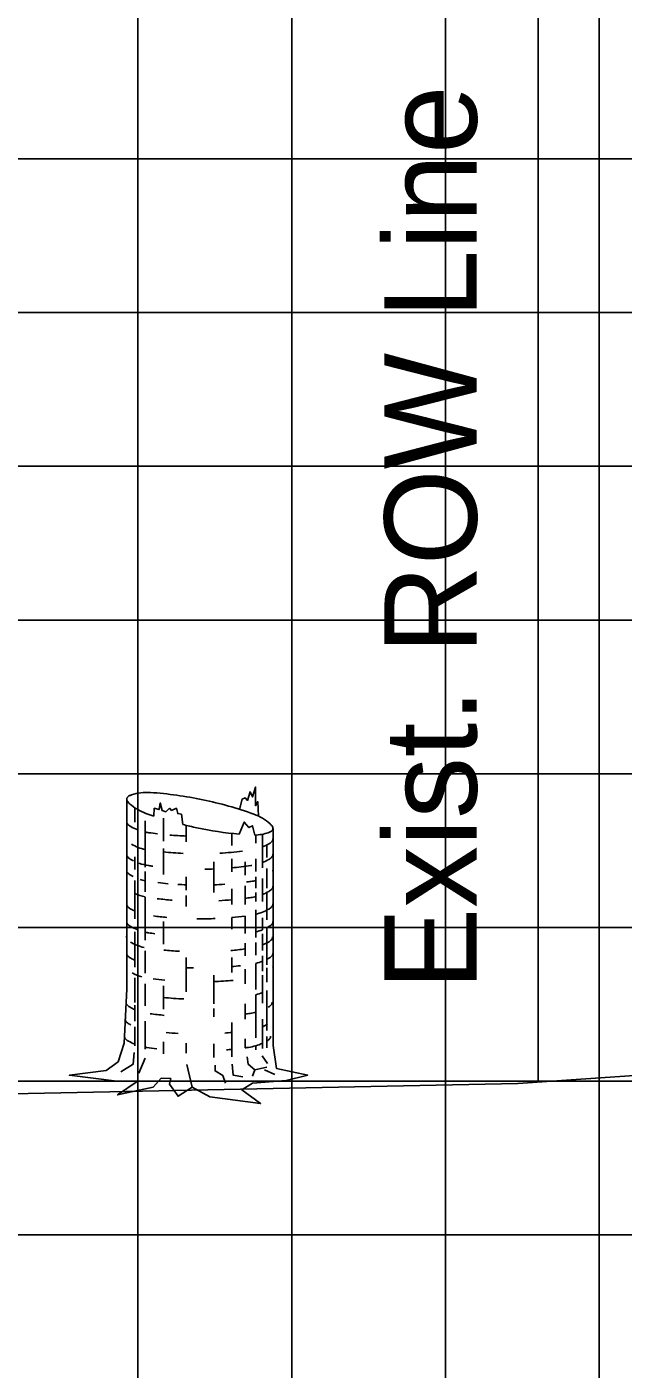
# Model space of a CAD drawing. Extents: x 854676 to 854846, y 366268 to 366378.
# Drawn here: x 854725.38 to 854729.26, y 366362.44 to 366371.17 of the extents above; entities that cross this region are included whole.
import ezdxf

# ---------------------------------------------------------------- set-up
doc = ezdxf.new("R2010")
doc.units = 0
for name, color, linetype in [('E_ROW_Line', 7, 'Continuous'), ('MAJOR', 7, 'Continuous'), ('MINOR', 7, 'Continuous'), ('S_Roadway_Centerline', 7, 'Continuous'), ('S_Trees_Decid_NonPay', 7, 'Continuous')]:
    doc.layers.add(name, color=color, linetype=linetype)

msp = doc.modelspace()

# ---------------------------------------------------------------- linework, layer by layer
at = {"layer": 'E_ROW_Line'}
msp.add_line((854728.7092, 366364.3019), (854728.7092, 366374.3019), dxfattribs=at)
at = {"layer": 'MAJOR'}
for p, q in [((854729.1063, 366353.3091), (854729.1063, 366373.3091)), ((854689.1063, 366368.3091), (854829.1063, 366368.3091)), ((854689.1063, 366363.3091), (854829.1063, 366363.3091))]:
    msp.add_line(p, q, dxfattribs=at)
at = {"layer": 'MINOR'}
for p, q in [((854726.1063, 366353.3091), (854726.1063, 366373.3091)), ((854727.1063, 366353.3091), (854727.1063, 366373.3091)), ((854728.1063, 366353.3091), (854728.1063, 366373.3091)), ((854689.1063, 366370.3091), (854829.1063, 366370.3091)), ((854689.1063, 366369.3091), (854829.1063, 366369.3091)), ((854689.1063, 366367.3091), (854829.1063, 366367.3091)), ((854689.1063, 366366.3091), (854829.1063, 366366.3091)), ((854689.1063, 366365.3091), (854829.1063, 366365.3091)), ((854689.1063, 366364.3091), (854829.1063, 366364.3091))]:
    msp.add_line(p, q, dxfattribs=at)
at = {"layer": 'S_Roadway_Centerline'}
msp.add_lwpolyline([(854696.3673, 366363.2907), (854702.4938, 366363.7061), (854707.8783, 366363.8716), (854728.5765, 366364.293), (854734.737, 366364.7173), (854737.8845, 366365.0609), (854738.3684, 366365.0916), (854742.1275, 366364.878), (854742.2093, 366364.875), (854748.431, 366365.0464), (854748.4566, 366365.0475), (854748.494, 366365.05), (854750.6841, 366365.0857), (854759.8334, 366365.231), (854760.071, 366365.2256), (854771.0875, 366364.9954)], dxfattribs=at)
at = {"layer": 'S_Trees_Decid_NonPay'}
for p, q in [((854726.085, 366366.0887), (854726.085, 366365.9942)), ((854726.1532, 366366.0021), (854726.1532, 366365.7016)), ((854726.272, 366366.0191), (854726.272, 366365.8709)), ((854726.419, 366365.9732), (854726.419, 366365.8663)), ((854726.7162, 366365.9207), (854726.7162, 366365.842)), ((854726.9163, 366365.9155), (854726.9163, 366365.6976)), ((854726.8737, 366365.9102), (854726.8737, 366365.8584)), ((854726.9432, 366365.8453), (854726.9432, 366365.7632)), ((854726.085, 366365.7678), (854726.085, 366365.6852)), ((854726.272, 366365.823), (854726.272, 366365.6543)), ((854726.7162, 366365.7554), (854726.7162, 366365.6707)), ((854726.8737, 366365.7554), (854726.8737, 366365.6727)), ((854726.1532, 366365.6727), (854726.1532, 366365.5415)), ((854726.5987, 366365.737), (854726.5987, 366365.5369)), ((854726.8028, 366365.737), (854726.8028, 366365.6504)), ((854726.9432, 366365.6937), (854726.9432, 366365.5638)), ((854726.085, 366365.6156), (854726.085, 366365.3643)), ((854726.419, 366365.6379), (854726.419, 366365.5513)), ((854726.8028, 366365.5802), (854726.8028, 366365.4588)), ((854726.8737, 366365.6379), (854726.8737, 366365.5638)), ((854726.9163, 366365.6287), (854726.9163, 366365.4772)), ((854726.1532, 366365.5073), (854726.1532, 366365.2265)), ((854726.419, 366365.5165), (854726.419, 366365.4463)), ((854726.7162, 366365.5598), (854726.7162, 366365.4588)), ((854726.8737, 366365.5369), (854726.8737, 366365.4772)), ((854726.9432, 366365.5415), (854726.9432, 366365.3597)), ((854726.8737, 366365.424), (854726.8737, 366365.2429)), ((854726.272, 366365.3479), (854726.272, 366365.1996)), ((854726.7162, 366365.3741), (854726.7162, 366365.298)), ((854726.8028, 366365.3833), (854726.8028, 366365.2691)), ((854726.9163, 366365.3722), (854726.9163, 366365.2941)), ((854726.9432, 366365.3125), (854726.9432, 366365.0657)), ((854726.085, 366365.2816), (854726.085, 366365.0513)), ((854726.9163, 366365.2672), (854726.9163, 366365.1602)), ((854726.1532, 366365.1563), (854726.1532, 366365.0119)), ((854726.8028, 366365.2075), (854726.8028, 366365.1254)), ((854726.8737, 366365.2114), (854726.8737, 366365.1294)), ((854726.419, 366365.113), (854726.419, 366364.8905)), ((854726.7162, 366365.113), (854726.7162, 366365.0159)), ((854726.8737, 366365.0756), (854726.8737, 366364.905)), ((854726.9163, 366365.1254), (854726.9163, 366365.0244)), ((854726.9432, 366365.0467), (854726.9432, 366364.9522)), ((854726.085, 366364.9811), (854726.085, 366364.8203)), ((854726.5987, 366364.9995), (854726.5987, 366364.8125)), ((854726.8028, 366365.0388), (854726.8028, 366364.9417)), ((854726.9163, 366364.9988), (854726.9163, 366364.8164)), ((854726.1532, 366364.9417), (854726.1532, 366364.8)), ((854726.272, 366364.9299), (854726.272, 366364.777)), ((854726.8737, 366364.8715), (854726.8737, 366364.592)), ((854726.9452, 366364.8991), (854726.9439, 366364.6392)), ((854726.085, 366364.8039), (854726.085, 366364.6989)), ((854726.5987, 366364.7816), (854726.5987, 366364.7285)), ((854726.8028, 366364.8125), (854726.8028, 366364.7134)), ((854726.1532, 366364.6989), (854726.1532, 366364.5178)), ((854726.9163, 366364.7134), (854726.9163, 366364.5218)), ((854726.085, 366364.6622), (854726.085, 366364.5382)), ((854726.7162, 366364.6911), (854726.7162, 366364.4667)), ((854726.272, 366364.5651), (854726.272, 366364.487)), ((854726.419, 366364.5572), (854726.419, 366364.4909)), ((854726.5987, 366364.5526), (854726.5987, 366364.4621)), ((854726.8028, 366364.5841), (854726.8028, 366364.5257)), ((854726.8737, 366364.5395), (854726.8737, 366364.5139)), ((854726.9432, 366364.6005), (854726.9432, 366364.5264)), ((854726.1526, 366364.4581), (854726.1112, 366364.3617)), ((854726.9144, 366364.4745), (854726.9491, 366364.4233)), ((854726.459, 366364.2711), (854726.4242, 366364.4168)), ((854726.9964, 366364.3531), (854726.9288, 366364.384))]:
    msp.add_line(p, q, dxfattribs=at)
for points in [[(854726.8894, 366366.0336), (854726.8855, 366366.1281), (854726.8711, 366366.1012), (854726.8711, 366366.2226), (854726.8501, 366366.1589), (854726.8356, 366366.1917), (854726.8192, 366366.1359), (854726.8028, 366366.153), (854726.7844, 366366.1445), (854726.7654, 366366.0775)], [(854726.9846, 366365.9529), (854726.9846, 366364.5408), (854727.0069, 366364.3925), (854727.2103, 366364.3492), (854727.0705, 366364.3138), (854726.852, 366364.2954), (854726.7825, 366364.2521), (854726.9039, 366364.1635), (854726.5725, 366364.2068), (854726.459, 366364.2711), (854726.3665, 366364.2108), (854726.3107, 366364.2895), (854726.3192, 366364.3262), (854726.2575, 366364.3282), (854726.2057, 366364.2711), (854725.9734, 366364.2193), (854726.1007, 366364.3079), (854725.9688, 366364.3098), (854725.6604, 366364.3472), (854725.8993, 366364.3781), (854725.9774, 366364.4358), (854726.0161, 366364.5572), (854726.0331, 366364.9109), (854726.0331, 366366.1445)], [(854726.3973, 366365.9785), (854726.3888, 366366.0454), (854726.3645, 366366.05), (854726.356, 366366.0848), (854726.3251, 366366.0703), (854726.3107, 366366.0848), (854726.2864, 366366.0618), (854726.2634, 366366.0703), (854726.251, 366366.1195), (854726.2431, 366366.0762), (854726.2123, 366366.0848), (854726.209, 366366.0336)], [(854726.8671, 366365.9096), (854726.8501, 366365.9712), (854726.8278, 366365.9594), (854726.7969, 366365.9942), (854726.7634, 366365.9161)], [(854726.0823, 366364.4955), (854726.0738, 366364.4188), (854725.9957, 366364.3695)], [(854726.8665, 366364.384), (854726.8232, 366364.4188), (854726.8153, 366364.4667)], [(854726.6073, 366364.4128), (854726.6073, 366364.3761), (854726.6585, 366364.3453), (854726.6755, 366364.2954)], [(854726.7188, 366364.4188), (854726.7247, 366364.3492), (854726.7884, 366364.3367)], [(854726.9452, 366364.4004), (854726.8665, 366364.384), (854726.8501, 366364.3407)]]:
    msp.add_lwpolyline(points, dxfattribs=at)
for centre, radius, start, end in [((854726.1644, 366365.8661), 0.3218, 86.05435, 108.17229), ((854726.0141, 366363.6862), 2.507, 78.17229, 86.05435), ((854726.0513, 366366.1445), 0.0179, 168.17229, 184.22782), ((854726.0571, 366366.145), 0.0237, 184.22782, 198.17229), ((854726.0513, 366366.1445), 0.0179, 152.11676, 168.17229), ((854726.0665, 366366.1481), 0.0336, 198.17229, 216.94859), ((854726.0565, 366366.1418), 0.0237, 138.17229, 152.11676), ((854726.0638, 366366.1352), 0.0336, 119.39599, 138.17229), ((854726.1144, 366366.1841), 0.0935, 216.9486, 228.17229), ((854726.0932, 366366.083), 0.0935, 108.17229, 119.39599), ((854726.2667, 366366.3542), 0.3218, 228.17229, 250.29024), ((854726.0141, 366363.6862), 2.507, 70.29024, 78.17229), ((854726.0517, 366365.9971), 0.0191, 163.94846, 180), ((854727.0036, 366368.4113), 2.507, 250.29024, 251.52809), ((854726.751, 366365.7433), 0.3218, 48.17229, 70.29024), ((854726.0517, 366365.9971), 0.0191, 180, 196.05154), ((854726.0576, 366365.9988), 0.0252, 196.05154, 210), ((854726.0667, 366366.004), 0.0356, 210, 228.74941), ((854726.1081, 366366.0513), 0.0984, 228.74941, 240), ((854726.2219, 366366.2484), 0.3261, 240, 248.32432), ((854726.2219, 366366.2484), 0.3261, 257.8036, 261.8968), ((854726.5081, 366368.2585), 2.3564, 261.8968, 263.27991), ((854727.0036, 366368.4113), 2.507, 255.99867, 258.17229), ((854727.0036, 366368.4113), 2.507, 258.17229, 264.50134), ((854726.8532, 366366.2314), 0.3218, 272.44787, 288.17229), ((854726.9245, 366366.0144), 0.0935, 288.17229, 299.39599), ((854726.9033, 366365.9134), 0.0935, 36.9486, 48.17229), ((854726.9539, 366365.9622), 0.0336, 299.39599, 318.17229), ((854726.9512, 366365.9494), 0.0336, 18.17229, 36.94859), ((854726.9612, 366365.9556), 0.0237, 318.17229, 332.11676), ((854726.9663, 366365.9529), 0.0179, 332.11676, 348.17229), ((854726.9606, 366365.9525), 0.0237, 4.22782, 18.17229), ((854726.9663, 366365.9529), 0.0179, 348.17229, 4.22783), ((854726.2219, 366366.1352), 0.3261, 240.90989, 257.8036), ((854726.5081, 366368.2585), 2.3564, 265.24001, 267.83857), ((854726.7943, 366366.1352), 0.3261, 291.95057, 300), ((854726.9081, 366365.938), 0.0984, 300, 311.25059), ((854726.9495, 366365.8908), 0.0356, 311.25059, 330), ((854726.9586, 366365.8856), 0.0252, 330, 343.94846), ((854726.9645, 366365.8839), 0.0191, 343.94846, 360), ((854726.9645, 366365.8839), 0.0191, 360, 6.11276), ((854726.0517, 366365.783), 0.0191, 163.94846, 180), ((854726.0517, 366365.783), 0.0191, 180, 196.05154), ((854726.0576, 366365.7847), 0.0252, 196.05154, 210), ((854726.0667, 366365.7899), 0.0356, 210, 228.74941), ((854726.1081, 366365.8371), 0.0984, 228.74941, 240), ((854726.2219, 366366.0343), 0.3261, 240, 243.57187), ((854726.5081, 366368.1452), 2.3564, 264.24201, 267.36728), ((854726.5081, 366368.1452), 2.3564, 273.14807, 276.77338), ((854726.7943, 366366.0343), 0.3261, 291.95057, 300), ((854726.9081, 366365.8371), 0.0984, 300, 311.25059), ((854726.9495, 366365.7899), 0.0356, 311.25059, 330), ((854726.9586, 366365.7847), 0.0252, 330, 343.94846), ((854726.9645, 366365.783), 0.0191, 343.94846, 360), ((854726.9645, 366365.783), 0.0191, 360, 6.11276), ((854726.0517, 366365.6801), 0.0191, 163.94846, 180), ((854726.0517, 366365.6801), 0.0191, 180, 196.05154), ((854726.0576, 366365.6818), 0.0252, 196.05154, 210), ((854726.0667, 366365.687), 0.0356, 210, 228.74941), ((854726.1081, 366365.7342), 0.0984, 228.74941, 240), ((854726.2219, 366366.0343), 0.3261, 250.41675, 261.8968), ((854726.5081, 366368.0443), 2.3564, 261.8968, 262.55191), ((854726.5081, 366368.0443), 2.3564, 270.81188, 272.1981), ((854726.5081, 366368.0443), 2.3564, 275.06468, 278.1032), ((854726.7943, 366366.0343), 0.3261, 278.1032, 279.08543), ((854726.9645, 366365.6801), 0.0191, 343.94846, 360), ((854726.9645, 366365.6801), 0.0191, 360, 6.11276), ((854726.2219, 366365.9314), 0.3261, 240, 243.24303), ((854726.2219, 366365.9314), 0.3261, 251.68306, 257.8036), ((854726.5081, 366367.9414), 2.3564, 263.34129, 264.99462), ((854726.5081, 366367.9414), 2.3564, 266.50356, 267.83857), ((854726.5081, 366367.9414), 2.3564, 272.1981, 273.97408), ((854726.5081, 366367.9414), 2.3564, 277.38384, 278.1032), ((854726.7943, 366365.9314), 0.3261, 278.1032, 284.03823), ((854726.9586, 366365.5767), 0.0252, 330, 343.94846), ((854726.9645, 366365.575), 0.0191, 343.94846, 360), ((854726.9645, 366365.575), 0.0191, 360, 6.11276), ((854726.2219, 366365.8263), 0.3261, 245.15448, 257.8036), ((854726.5081, 366367.8364), 2.3564, 263.26817, 265.63617), ((854726.5081, 366367.8364), 2.3564, 273.0067, 275.06467), ((854726.5081, 366367.8364), 2.3564, 277.18685, 278.1032), ((854726.7943, 366365.8263), 0.3261, 278.1032, 284.03823), ((854726.7943, 366365.8263), 0.3261, 291.95057, 300), ((854726.9081, 366365.6292), 0.0984, 300, 311.25059), ((854726.9495, 366365.582), 0.0356, 311.25059, 330), ((854726.0517, 366365.46), 0.0191, 163.94846, 180), ((854726.0517, 366365.46), 0.0191, 180, 196.05154), ((854726.0576, 366365.4617), 0.0252, 196.05154, 210), ((854726.0667, 366365.4669), 0.0356, 210, 228.74941), ((854726.1081, 366365.5141), 0.0984, 228.74941, 240), ((854726.2219, 366365.7113), 0.3261, 240, 245.15448), ((854726.7943, 366365.7113), 0.3261, 284.03823, 300), ((854726.9081, 366365.5141), 0.0984, 300, 311.25059), ((854726.9495, 366365.4669), 0.0356, 311.25059, 330), ((854726.9586, 366365.4617), 0.0252, 330, 343.94846), ((854726.9645, 366365.46), 0.0191, 343.94846, 360), ((854726.9645, 366365.46), 0.0191, 360, 6.11276), ((854726.0525, 366365.3456), 0.0191, 163.94846, 180), ((854726.0525, 366365.3456), 0.0191, 180, 196.05154), ((854726.0584, 366365.3473), 0.0252, 196.05154, 210), ((854726.0674, 366365.3525), 0.0356, 210, 228.74941), ((854726.1088, 366365.3997), 0.0984, 228.74941, 240), ((854726.2227, 366365.5969), 0.3261, 240, 247.86558), ((854726.5081, 366367.7213), 2.3564, 262.65877, 264.79114), ((854726.5081, 366367.7213), 2.3564, 269.55779, 270), ((854726.5081, 366367.7213), 2.3564, 270, 272.414), ((854726.5081, 366367.7213), 2.3564, 275.06467, 277.18685), ((854726.795, 366365.5969), 0.3261, 297.00583, 300), ((854726.9089, 366365.3997), 0.0984, 300, 311.25059), ((854726.9503, 366365.3525), 0.0356, 311.25059, 330), ((854726.9593, 366365.3473), 0.0252, 330, 343.94846), ((854726.9652, 366365.3456), 0.0191, 343.94846, 360), ((854726.9652, 366365.3456), 0.0191, 0, 6.11277), ((854726.0493, 366365.2453), 0.0191, 163.94846, 180), ((854726.2227, 366365.5969), 0.3261, 257.66994, 261.8968), ((854726.5088, 366367.6069), 2.3564, 261.8968, 262.86151), ((854726.795, 366365.5969), 0.3261, 283.90364, 291.80982), ((854726.9057, 366365.2994), 0.0984, 300, 311.25059), ((854726.9471, 366365.2522), 0.0356, 311.25059, 330), ((854726.9562, 366365.247), 0.0252, 330, 343.94846), ((854726.9621, 366365.2453), 0.0191, 343.94846, 360), ((854726.9621, 366365.2453), 0.0191, 0, 6.11277), ((854726.0517, 366365.1406), 0.0191, 163.94846, 180), ((854726.0517, 366365.1406), 0.0191, 180, 196.05154), ((854726.0576, 366365.1423), 0.0252, 196.05154, 210), ((854726.0667, 366365.1475), 0.0356, 210, 228.74941), ((854726.2195, 366365.4966), 0.3261, 240, 256.90786), ((854726.5057, 366367.5067), 2.3564, 264.3443, 266.85288), ((854726.5057, 366367.5067), 2.3564, 274.97344, 277.24554), ((854726.7919, 366365.4966), 0.3261, 292.40493, 300), ((854726.9495, 366365.1475), 0.0356, 311.25059, 330), ((854726.9586, 366365.1423), 0.0252, 330, 343.94846), ((854726.9645, 366365.1406), 0.0191, 343.94846, 360), ((854726.9645, 366365.1406), 0.0191, 360, 6.11276), ((854726.1081, 366365.1947), 0.0984, 228.74941, 240), ((854726.2219, 366365.3919), 0.3261, 240, 245.15448), ((854726.5081, 366367.4019), 2.3564, 267.83857, 269.00542), ((854726.5081, 366367.4019), 2.3564, 275.06467, 276.42799), ((854726.7943, 366365.3919), 0.3261, 284.03823, 291.95057), ((854726.7943, 366365.3919), 0.3261, 297.15252, 300), ((854726.9081, 366365.1947), 0.0984, 300, 311.25059), ((854726.9645, 366365.05), 0.0191, 360, 6.11276), ((854726.2219, 366365.3013), 0.3261, 241.93896, 253.9183), ((854726.5081, 366367.3113), 2.3564, 262.58433, 264.48651), ((854726.5081, 366367.3113), 2.3564, 272.1981, 275.27259), ((854726.7943, 366365.1881), 0.3261, 284.03823, 291.95057), ((854726.0477, 366364.8215), 0.0191, 163.94846, 180), ((854726.0477, 366364.8215), 0.0191, 180, 196.05154), ((854726.0536, 366364.8232), 0.0252, 196.05154, 210), ((854726.0626, 366364.8285), 0.0356, 210, 228.74941), ((854726.104, 366364.8757), 0.0984, 228.74941, 240), ((854726.2179, 366365.0728), 0.3261, 240, 245.93749), ((854726.5081, 366367.1981), 2.3564, 264.24201, 267.46903), ((854726.9041, 366364.8757), 0.0984, 300, 311.25059), ((854726.9455, 366364.8285), 0.0356, 311.25059, 330), ((854726.9545, 366364.8232), 0.0252, 330, 343.94846), ((854726.9604, 366364.8215), 0.0191, 343.94846, 360), ((854726.9604, 366364.8215), 0.0191, 360, 6.11276), ((854726.0428, 366364.7109), 0.0191, 163.94846, 180), ((854726.0428, 366364.7109), 0.0191, 180, 196.05154), ((854726.0487, 366364.7126), 0.0252, 196.05154, 210), ((854726.0577, 366364.7178), 0.0356, 210, 228.74941), ((854726.504, 366367.0829), 2.3564, 262.22258, 264.4852), ((854726.504, 366367.0829), 2.3564, 277.28629, 278.1032), ((854726.7902, 366365.0728), 0.3261, 278.1032, 284.77414), ((854726.0373, 366364.6007), 0.0191, 163.94846, 180), ((854726.0991, 366364.7651), 0.0984, 228.74941, 240), ((854726.213, 366364.9622), 0.3261, 240, 241.90969), ((854726.4992, 366366.9723), 2.3564, 264.90887, 266.81578), ((854726.4992, 366366.9723), 2.3564, 274.18643, 275.28293), ((854726.7853, 366364.9622), 0.3261, 293.6544, 300), ((854726.0373, 366364.6007), 0.0191, 180, 196.05154), ((854726.0432, 366364.6024), 0.0252, 196.05154, 210), ((854726.0523, 366364.6076), 0.0356, 210, 228.74941), ((854726.0937, 366364.6548), 0.0984, 228.74941, 240), ((854726.2075, 366364.852), 0.3261, 240, 247.9161), ((854726.2075, 366364.852), 0.3261, 260.38342, 261.8968), ((854726.4937, 366366.862), 2.3564, 261.8968, 263.53328), ((854726.4937, 366366.862), 2.3564, 277.54032, 278.1032), ((854726.7799, 366364.852), 0.3261, 278.1032, 294.70938), ((854726.8937, 366364.6548), 0.0984, 300, 311.25059), ((854726.9351, 366364.6076), 0.0356, 311.25059, 330), ((854726.9441, 366364.6024), 0.0252, 330, 343.94846), ((854726.95, 366364.6007), 0.0191, 343.94846, 360), ((854726.95, 366364.6007), 0.0191, 0, 6.11277), ((854726.4937, 366366.862), 2.3564, 274.55512, 275.4167)]:
    msp.add_arc(centre, radius, start, end, dxfattribs=at)

# ---------------------------------------------------------------- texts
at = {"layer": 'E_ROW_Line'}
msp.add_text('Exist. ROW Line', height=0.6, rotation=90, dxfattribs=at).set_placement((854728.3092, 366364.9019))

doc.saveas('drawing.dxf')
